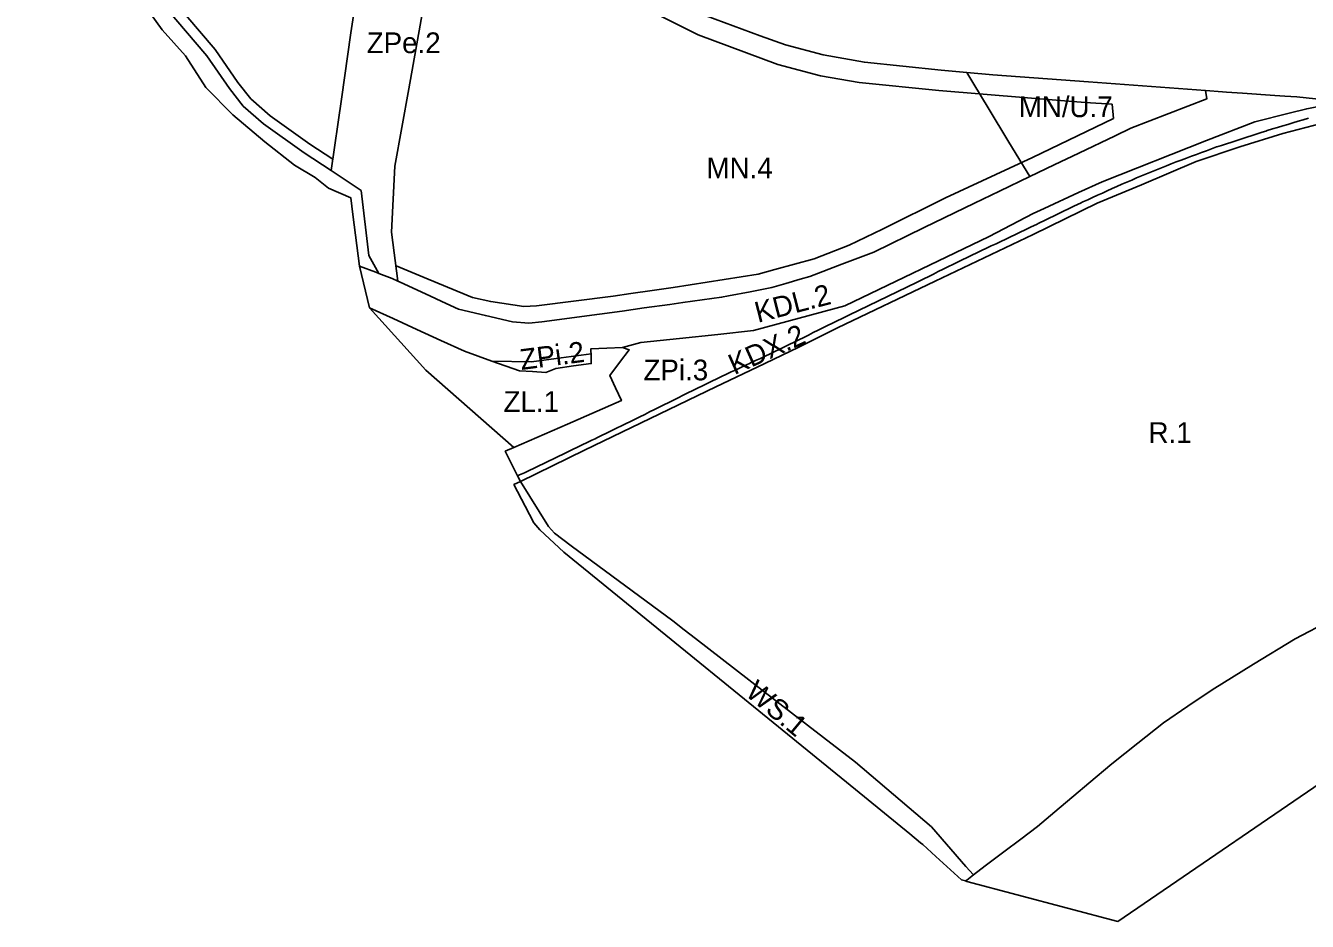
# Model space of a CAD drawing. Extents: x 7431080 to 7433370, y 5546450 to 5548428.
# Drawn here: x 7431158.2 to 7431653, y 5546497.2 to 5546842.9 of the extents above; entities that cross this region are included whole.
import ezdxf

# ---------------------------------------------------------------- set-up
doc = ezdxf.new("R2010")
doc.units = 0
for name, color, linetype in [('Linie Rozgraniczajace', 7, 'Continuous'), ('nieprzekraczalna linia zabudowy', 7, 'Continuous'), ('oznaczenia_przeznaczen', 7, 'Continuous')]:
    doc.layers.add(name, color=color, linetype=linetype)

msp = doc.modelspace()

# ---------------------------------------------------------------- linework, layer by layer
at = {"layer": 'Linie Rozgraniczajace'}
msp.add_line((7431206.35, 5546856.98), (7431228.24, 5546831.3), dxfattribs=at)
for points in [[(7431323.53, 5546904.99), (7431317.61, 5546882.92), (7431306.12, 5546818.57), (7431300.78, 5546788.7), (7431299.43, 5546763.16), (7431301.94, 5546744.32)], [(7431521.53, 5546824.88), (7431511.67, 5546825.76), (7431482.02, 5546828.79), (7431466.14, 5546831.59), (7431451.55, 5546835.5), (7431441.76, 5546839.01), (7431420.92, 5546846.64), (7431410.25, 5546851.77), (7431404.56, 5546854.76), (7431397.4, 5546858.52), (7431373.5, 5546873.38), (7431325.81, 5546903.54), (7431323.53, 5546904.99)], [(7431670.62, 5546559.16), (7431579.86, 5546497.22), (7431521.6, 5546512.65), (7431521.01, 5546512.81), (7431519.53, 5546513.2), (7431509.61, 5546522.26), (7431504.52, 5546526.83), (7431503.71, 5546527.56), (7431499.58, 5546531), (7431478.62, 5546548.05), (7431366.04, 5546639.65), (7431356.68, 5546648.38), (7431354.45, 5546651.02), (7431351.06, 5546657.47), (7431346.75, 5546665.8), (7431349.23, 5546667.02), (7431348.16, 5546669.14), (7431343.36, 5546678.68), (7431346.66, 5546680.1), (7431312.76, 5546709.94), (7431290.94, 5546734.05), (7431287.08, 5546750.11), (7431284.53, 5546770.04), (7431283.71, 5546776.49), (7431275.2, 5546780.25), (7431270.03, 5546784.34), (7431262.03, 5546789.12), (7431250.56, 5546798.06), (7431238.18, 5546808.47), (7431227.81, 5546819.07), (7431219.93, 5546831.24), (7431210.9, 5546841.34), (7431201.62, 5546854.25)], [(7431276.17, 5546786.99), (7431280.14, 5546814.58), (7431283.78, 5546840.11), (7431285.51, 5546851.9)], [(7431287.8, 5546779.34), (7431276.17, 5546786.99), (7431265.73, 5546793.87), (7431250.1, 5546804.98), (7431242.27, 5546811.86), (7431236.88, 5546818.64), (7431228.24, 5546831.3)], [(7431521.53, 5546824.88), (7431524.23, 5546820.32), (7431529.78, 5546811.15), (7431537.8, 5546797.89), (7431545.83, 5546784.63)], [(7431613.63, 5546817.91), (7431568.51, 5546821.25), (7431531.59, 5546823.99), (7431521.53, 5546824.88)], [(7431397.02, 5546733.95), (7431406.9, 5546735.31), (7431411.95, 5546736.01), (7431426.88, 5546738.07), (7431429.5, 5546738.58), (7431437.87, 5546740.22), (7431446.24, 5546741.86), (7431451.74, 5546743.46), (7431457.24, 5546745.07), (7431460.97, 5546746.16), (7431473.34, 5546750.82), (7431485.72, 5546755.47), (7431505.13, 5546764.95), (7431524.54, 5546774.42), (7431534.11, 5546779.01), (7431545.83, 5546784.63), (7431555.3, 5546789.17), (7431564.78, 5546793.72), (7431578.8, 5546800.41), (7431584.85, 5546803.32), (7431599.53, 5546809.02), (7431614.21, 5546814.72), (7431613.63, 5546817.91)], [(7431613.63, 5546817.91), (7431620.23, 5546817.42), (7431621.77, 5546817.3), (7431628, 5546816.84), (7431640.51, 5546815.97), (7431644.37, 5546815.71), (7431648.98, 5546815.38), (7431659.79, 5546814.25)], [(7431666.52, 5546813.54), (7431652.76, 5546810.83), (7431646.05, 5546809.19), (7431632.69, 5546805.73), (7431614.04, 5546798.55), (7431573.8, 5546782.64), (7431564.7, 5546778.48), (7431551.36, 5546772.34), (7431547.12, 5546770.36), (7431530.22, 5546761.49), (7431474.45, 5546734.76), (7431439.19, 5546725.31), (7431425.46, 5546723.7), (7431410.61, 5546722.15), (7431395.76, 5546720.59), (7431388.63, 5546718.7)], [(7431456.45, 5546718.75), (7431471.59, 5546726.27), (7431509.4, 5546744.32), (7431547.2, 5546762.37), (7431571.9, 5546774.39), (7431588.96, 5546781.5), (7431610.07, 5546790.44), (7431627, 5546796.1), (7431643.53, 5546801.34), (7431658.3, 5546805.17), (7431664.35, 5546806.81), (7431674.43, 5546808.97), (7431688.31, 5546811.48)], [(7431653.39, 5546807.2), (7431651.41, 5546806.6), (7431649.43, 5546806.01), (7431647.45, 5546805.41), (7431645.48, 5546804.82), (7431643.5, 5546804.22), (7431641.52, 5546803.63), (7431639.54, 5546803.03), (7431637.56, 5546802.44), (7431636.95, 5546802.25), (7431635.6, 5546801.81), (7431633.63, 5546801.18), (7431631.67, 5546800.54), (7431629.7, 5546799.9), (7431627.74, 5546799.27), (7431625.77, 5546798.63), (7431623.81, 5546798), (7431621.84, 5546797.36), (7431619.88, 5546796.72), (7431618.01, 5546796.12), (7431617.91, 5546796.08), (7431615.98, 5546795.36), (7431614.04, 5546794.64), (7431612.1, 5546793.92), (7431610.17, 5546793.21), (7431608.23, 5546792.49), (7431606.3, 5546791.77), (7431604.36, 5546791.05), (7431602.42, 5546790.33), (7431600.49, 5546789.61), (7431598.58, 5546788.83), (7431596.67, 5546788.04), (7431594.75, 5546787.26), (7431592.84, 5546786.48), (7431590.93, 5546785.69), (7431589.02, 5546784.91), (7431587.11, 5546784.12), (7431585.2, 5546783.34), (7431583.29, 5546782.56), (7431582.04, 5546782.04), (7431581.39, 5546781.75), (7431579.51, 5546780.89), (7431577.63, 5546780.02), (7431575.76, 5546779.16), (7431573.88, 5546778.3), (7431572, 5546777.44), (7431570.13, 5546776.58), (7431568.25, 5546775.72), (7431566.37, 5546774.86), (7431565.43, 5546774.43), (7431564.5, 5546773.98), (7431562.65, 5546773.07), (7431560.79, 5546772.17), (7431558.93, 5546771.27), (7431557.07, 5546770.36), (7431555.22, 5546769.46), (7431553.36, 5546768.56), (7431551.5, 5546767.65), (7431549.64, 5546766.75), (7431548.15, 5546766.02), (7431547.78, 5546765.85), (7431545.92, 5546764.97), (7431544.05, 5546764.08), (7431542.19, 5546763.19), (7431540.32, 5546762.31), (7431538.45, 5546761.42), (7431536.59, 5546760.54), (7431534.72, 5546759.65), (7431532.86, 5546758.77), (7431530.99, 5546757.88), (7431529.13, 5546756.98), (7431527.27, 5546756.09), (7431525.41, 5546755.19), (7431523.55, 5546754.3), (7431521.69, 5546753.4), (7431519.82, 5546752.51), (7431517.96, 5546751.61), (7431516.1, 5546750.72), (7431514.5, 5546749.95), (7431514.24, 5546749.82), (7431512.39, 5546748.9), (7431510.54, 5546747.98), (7431508.7, 5546747.06), (7431506.85, 5546746.14), (7431505, 5546745.22), (7431503.15, 5546744.3), (7431501.3, 5546743.38), (7431499.45, 5546742.46), (7431497.9, 5546741.68)], [(7431294.59, 5546747.28), (7431290.69, 5546754.23), (7431287.8, 5546779.34)], [(7431294.59, 5546747.28), (7431293.44, 5546747.71), (7431287.08, 5546750.11)], [(7431301.94, 5546744.32), (7431299.79, 5546745.32), (7431294.59, 5546747.28)], [(7431301.94, 5546744.32), (7431302.84, 5546743.9), (7431312.54, 5546739.38), (7431320.55, 5546735.72), (7431325.29, 5546733.44), (7431335.75, 5546731.01), (7431346.2, 5546728.59), (7431352.53, 5546728.05), (7431357.51, 5546728.55), (7431379.75, 5546731.5), (7431388.46, 5546732.74), (7431397.02, 5546733.95)], [(7431497.9, 5546741.68), (7431497.6, 5546741.54), (7431495.73, 5546740.65), (7431493.87, 5546739.77), (7431492, 5546738.88), (7431490.14, 5546737.99), (7431488.27, 5546737.1), (7431486.41, 5546736.22), (7431484.54, 5546735.33), (7431482.68, 5546734.44), (7431480.81, 5546733.55), (7431480.26, 5546733.29), (7431478.96, 5546732.65), (7431477.1, 5546731.74), (7431475.25, 5546730.82), (7431473.4, 5546729.91), (7431471.54, 5546729), (7431469.69, 5546728.09), (7431467.84, 5546727.18), (7431465.99, 5546726.26), (7431464.13, 5546725.35), (7431462.28, 5546724.44), (7431460.43, 5546723.52), (7431458.58, 5546722.61), (7431456.72, 5546721.7), (7431454.87, 5546720.78), (7431453.02, 5546719.87), (7431451.17, 5546718.95), (7431449.32, 5546718.04), (7431447.46, 5546717.13), (7431446.37, 5546716.58), (7431445.6, 5546716.23), (7431443.73, 5546715.36), (7431441.86, 5546714.49), (7431439.98, 5546713.62), (7431438.11, 5546712.75), (7431437.95, 5546712.67), (7431436.24, 5546711.87), (7431434.37, 5546711), (7431432.49, 5546710.13), (7431430.62, 5546709.26), (7431429.53, 5546708.75), (7431428.75, 5546708.38), (7431426.9, 5546707.47)], [(7431346.66, 5546680.1), (7431367.45, 5546689.17), (7431388.23, 5546698.24), (7431385.99, 5546703.08), (7431383.74, 5546707.93), (7431387.5, 5546712.86), (7431391.25, 5546717.78), (7431388.63, 5546718.7), (7431382.54, 5546718.46), (7431376.44, 5546718.21), (7431376.46, 5546717.21), (7431376.49, 5546716.22), (7431376.54, 5546714.37), (7431376.58, 5546712.51), (7431369.76, 5546711.58), (7431362.94, 5546710.65), (7431359, 5546709.09), (7431353.94, 5546709.38), (7431348.87, 5546709.68), (7431338.26, 5546713.46), (7431327.65, 5546717.23), (7431318.48, 5546721.44), (7431309.3, 5546725.64), (7431300.12, 5546729.84), (7431290.94, 5546734.05)], [(7431456.45, 5546718.75), (7431440.58, 5546711.12), (7431424.71, 5546703.48), (7431373.98, 5546679.1), (7431361.61, 5546673.06), (7431349.23, 5546667.02)], [(7431376.49, 5546716.22), (7431365.02, 5546714.71), (7431353.55, 5546713.21), (7431338.26, 5546713.46)], [(7431426.9, 5546707.47), (7431425.04, 5546706.57), (7431423.18, 5546705.67), (7431421.33, 5546704.76), (7431419.47, 5546703.86), (7431417.61, 5546702.95), (7431415.75, 5546702.05), (7431413.9, 5546701.15), (7431412.04, 5546700.24), (7431410.19, 5546699.32), (7431408.34, 5546698.4), (7431406.49, 5546697.48), (7431404.64, 5546696.56), (7431402.79, 5546695.65), (7431400.94, 5546694.73), (7431399.09, 5546693.81), (7431397.24, 5546692.89), (7431395.39, 5546691.97), (7431393.54, 5546691.06), (7431391.69, 5546690.15), (7431389.83, 5546689.24), (7431387.98, 5546688.33), (7431386.89, 5546687.8), (7431386.12, 5546687.42), (7431384.27, 5546686.51), (7431382.41, 5546685.6), (7431380.56, 5546684.69), (7431378.7, 5546683.78), (7431378.07, 5546683.48), (7431376.85, 5546682.89), (7431374.98, 5546681.99), (7431373.12, 5546681.1), (7431371.26, 5546680.2), (7431369.4, 5546679.31), (7431367.54, 5546678.41), (7431365.68, 5546677.52), (7431363.81, 5546676.62), (7431361.95, 5546675.73), (7431360.09, 5546674.84), (7431358.23, 5546673.95), (7431356.36, 5546673.06), (7431354.5, 5546672.17), (7431352.64, 5546671.28), (7431350.77, 5546670.38), (7431348.91, 5546669.49), (7431348.16, 5546669.14)], [(7431349.23, 5546667.02), (7431360.08, 5546649.57), (7431361.25, 5546648.29), (7431362.43, 5546647.02)], [(7431362.43, 5546647.02), (7431365.64, 5546644.6), (7431368.85, 5546642.18), (7431408.12, 5546613.18), (7431412.47, 5546609.75), (7431416.82, 5546606.33), (7431447.69, 5546582.49), (7431478.55, 5546558.64), (7431493.22, 5546546.15), (7431507.89, 5546533.65), (7431521.23, 5546518.36), (7431524.09, 5546515.12)], [(7431521.01, 5546512.81), (7431521.51, 5546513.18), (7431524.09, 5546515.12), (7431528.69, 5546518.59), (7431535.87, 5546524), (7431542.39, 5546528.9), (7431548.9, 5546533.81), (7431552.24, 5546536.63), (7431555.58, 5546539.45), (7431562.12, 5546544.98), (7431562.92, 5546545.66), (7431568.66, 5546550.51), (7431577.56, 5546558.03), (7431587.55, 5546565.96), (7431597.54, 5546573.89), (7431606.89, 5546580.26), (7431616.24, 5546586.64), (7431632.27, 5546596.43), (7431648.3, 5546606.21), (7431662.07, 5546613.48)]]:
    msp.add_lwpolyline(points, dxfattribs=at)
at = {"layer": 'nieprzekraczalna linia zabudowy'}
for points in [[(7431158.24, 5546935.82), (7431160.79, 5546928.37), (7431174.37, 5546913.06), (7431183.07, 5546900.34), (7431188.29, 5546891.72), (7431209.56, 5546859.39), (7431231.42, 5546833.73), (7431240.1, 5546821.02), (7431245.18, 5546814.63), (7431252.59, 5546808.12), (7431267.99, 5546797.17), (7431276.8, 5546791.37)], [(7431577.62, 5546812.63), (7431567.3, 5546813.26), (7431544.99, 5546815), (7431510.72, 5546817.85), (7431480.01, 5546820.97), (7431465.08, 5546823.54), (7431448.61, 5546827.9), (7431417.83, 5546839.36), (7431394.45, 5546851.12), (7431373.94, 5546863.8), (7431347.31, 5546880.59), (7431321.23, 5546896.87)], [(7431578.16, 5546807.07), (7431577.62, 5546812.63)], [(7431391.9, 5546739.48), (7431400.04, 5546740.65), (7431408.16, 5546741.82), (7431408.16, 5546741.82), (7431408.16, 5546741.82), (7431441.05, 5546746.99), (7431447.46, 5546748.77), (7431462.65, 5546752.96), (7431476.08, 5546758.14), (7431489.06, 5546764.36), (7431513.33, 5546776.4), (7431546.85, 5546792.06), (7431578.16, 5546807.07)], [(7431301.24, 5546750.25), (7431313.63, 5546745.13), (7431330.73, 5546738.01), (7431337.81, 5546736.44), (7431350.6, 5546734.58), (7431355.49, 5546734.78), (7431384.99, 5546738.49), (7431384.99, 5546738.49), (7431384.99, 5546738.49), (7431384.99, 5546738.49)], [(7431384.99, 5546738.49), (7431391.9, 5546739.48)]]:
    msp.add_lwpolyline(points, dxfattribs=at)

# ---------------------------------------------------------------- texts
at = {"layer": 'oznaczenia_przeznaczen'}
for s, p in [('ZPe.2', (7431289.9, 5546832.3)), ('ZPe.2', (7431289.9, 5546832.3)), ('ZPe.2', (7431289.9, 5546832.3)), ('ZPe.2', (7431289.9, 5546832.3)), ('MN/U.7', (7431541.61, 5546807.6)), ('MN/U.7', (7431541.61, 5546807.6)), ('MN/U.7', (7431541.61, 5546807.6)), ('MN.4', (7431421.06, 5546784.01)), ('MN.4', (7431421.06, 5546784.01)), ('MN.4', (7431421.06, 5546784.01)), ('ZPi.3', (7431396.74, 5546706.03)), ('ZPi.3', (7431396.74, 5546706.03)), ('ZPi.3', (7431396.74, 5546706.03)), ('ZPi.3', (7431396.74, 5546706.03)), ('ZL.1', (7431342.72, 5546693.84)), ('ZL.1', (7431342.72, 5546693.84)), ('ZL.1', (7431342.72, 5546693.84)), ('ZL.1', (7431342.72, 5546693.84)), ('R.1', (7431591.71, 5546681.85)), ('R.1', (7431591.71, 5546681.85)), ('R.1', (7431591.71, 5546681.85))]:
    msp.add_text(s, height=8, dxfattribs=at).set_placement(p)
for s, rotation, p in [('KDL.2', 14.3977, (7431440.88, 5546728.2)), ('KDL.2', 14.3977, (7431440.88, 5546728.2)), ('KDL.2', 14.3977, (7431440.88, 5546728.2)), ('KDL.2', 14.3977, (7431440.88, 5546728.2)), ('KDX.2', 24.2125, (7431431.82, 5546708)), ('KDX.2', 24.2125, (7431431.82, 5546708)), ('KDX.2', 24.2125, (7431431.82, 5546708)), ('KDX.2', 24.2125, (7431431.82, 5546708)), ('ZPi.2', 7.3506, (7431349.58, 5546710)), ('ZPi.2', 7.3506, (7431349.58, 5546710)), ('ZPi.2', 7.3506, (7431349.58, 5546710)), ('ZPi.2', 7.3506, (7431349.58, 5546710)), ('WS.1', 320.1541, (7431435.62, 5546584.75))]:
    msp.add_text(s, height=8, rotation=rotation, dxfattribs=at).set_placement(p)

doc.saveas('drawing.dxf')
